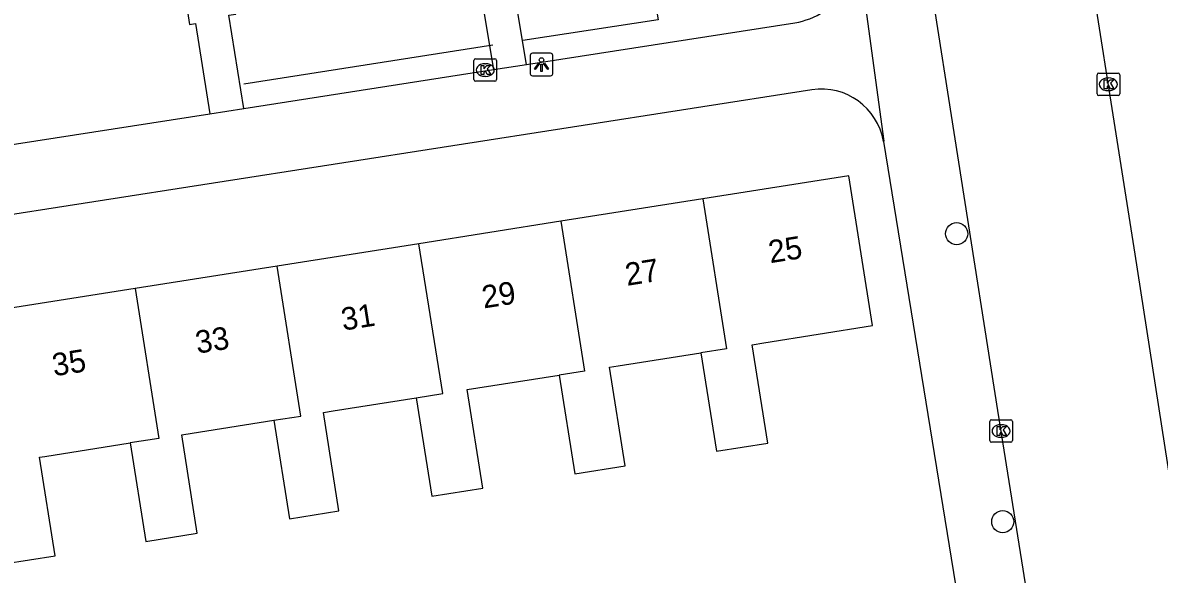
# Model space of a CAD drawing. Extents: x 160077 to 160945, y 386481 to 387498.
# Drawn here: x 160396 to 160446.3, y 387355.2 to 387379.6 of the extents above; entities that cross this region are included whole.
import ezdxf

# ---------------------------------------------------------------- set-up
doc = ezdxf.new("R2010")
doc.units = 0
for name, color, linetype in [('IMGEO_Boom', 7, 'Continuous'), ('IMGEO_Hek', 7, 'Continuous'), ('IMGEO_Kolk', 7, 'Continuous'), ('IMGEO_Lichtpunt', 7, 'Continuous'), ('IMGEO_Pand', 7, 'Continuous'), ('IMGEO_Pand_nummerreeks', 7, 'Continuous'), ('IMGEO_Rijbaan_lokaal_open', 7, 'Continuous'), ('IMGEO_Voetpad_open', 7, 'Continuous')]:
    doc.layers.add(name, color=color, linetype=linetype)

msp = doc.modelspace()

# ---------------------------------------------------------------- linework, layer by layer
at = {"layer": 'IMGEO_Boom'}
for centre in [(160437.295, 387370.245), (160439.333, 387357.508)]:
    msp.add_circle(centre, 0.489, dxfattribs=at)
at = {"layer": 'IMGEO_Hek'}
for points in [[(160423.651, 387382.448), (160424.101, 387379.701), (160418.122, 387378.788)], [(160416.789, 387378.59), (160405.787, 387376.859)]]:
    msp.add_lwpolyline(points, dxfattribs=at)
at = {"layer": 'IMGEO_Kolk'}
for p, q in [((160415.958, 387377.059), (160415.958, 387377.911)), ((160416.033, 387377.985), (160416.885, 387377.985)), ((160416.446, 387377.765), (160416.471, 387377.765)), ((160416.959, 387377.911), (160416.959, 387377.059)), ((160416.469, 387377.205), (160416.444, 387377.205)), ((160443.501, 387376.426), (160443.501, 387377.278)), ((160443.576, 387377.352), (160444.428, 387377.352)), ((160443.989, 387377.132), (160444.014, 387377.132)), ((160444.502, 387377.278), (160444.502, 387376.426)), ((160416.885, 387376.985), (160416.033, 387376.985)), ((160444.012, 387376.572), (160443.987, 387376.572)), ((160444.428, 387376.352), (160443.576, 387376.352)), ((160438.759, 387361.091), (160438.759, 387361.943)), ((160438.834, 387362.017), (160439.686, 387362.017)), ((160439.76, 387361.943), (160439.76, 387361.091)), ((160439.247, 387361.797), (160439.272, 387361.797)), ((160439.686, 387361.017), (160438.834, 387361.017)), ((160439.27, 387361.237), (160439.245, 387361.237))]:
    msp.add_line(p, q, dxfattribs=at)
for points in [[(160415.958, 387377.059), (160415.958, 387377.911)], [(160416.033, 387377.985), (160416.885, 387377.985)], [(160416.279, 387377.685), (160416.402, 387377.685), (160416.402, 387377.534), (160416.532, 387377.685), (160416.696, 387377.685), (160416.55, 387377.534), (160416.703, 387377.285), (160416.551, 387377.285), (160416.466, 387377.449), (160416.402, 387377.382), (160416.402, 387377.285), (160416.279, 387377.285), (160416.279, 387377.685)], [(160416.959, 387377.911), (160416.959, 387377.059)], [(160443.501, 387376.426), (160443.501, 387377.278)], [(160443.576, 387377.352), (160444.428, 387377.352)], [(160443.822, 387377.052), (160443.945, 387377.052), (160443.945, 387376.901), (160444.075, 387377.052), (160444.239, 387377.052), (160444.093, 387376.901), (160444.246, 387376.652), (160444.094, 387376.652), (160444.009, 387376.816), (160443.945, 387376.749), (160443.945, 387376.652), (160443.822, 387376.652), (160443.822, 387377.052)], [(160444.502, 387377.278), (160444.502, 387376.426)], [(160416.885, 387376.985), (160416.033, 387376.985)], [(160444.428, 387376.352), (160443.576, 387376.352)], [(160438.759, 387361.091), (160438.759, 387361.943)], [(160438.834, 387362.017), (160439.686, 387362.017)], [(160439.76, 387361.943), (160439.76, 387361.091)], [(160439.08, 387361.717), (160439.203, 387361.717), (160439.203, 387361.566), (160439.333, 387361.717), (160439.497, 387361.717), (160439.351, 387361.566), (160439.504, 387361.317), (160439.352, 387361.317), (160439.267, 387361.481), (160439.203, 387361.414), (160439.203, 387361.317), (160439.08, 387361.317), (160439.08, 387361.717)], [(160439.686, 387361.017), (160438.834, 387361.017)]]:
    msp.add_lwpolyline(points, dxfattribs=at)
for centre, start, end in [((160416.035, 387377.909), 91.552, 178.448), ((160416.035, 387377.909), 91.552, 178.448), ((160416.883, 387377.909), 1.552, 88.448), ((160416.883, 387377.909), 1.552, 88.448), ((160416.035, 387377.061), 181.552, 268.448), ((160416.035, 387377.061), 181.552, 268.448), ((160416.883, 387377.061), 271.552, 358.448), ((160416.883, 387377.061), 271.552, 358.448), ((160443.578, 387377.276), 91.552, 178.448), ((160443.578, 387377.276), 91.552, 178.448), ((160444.426, 387377.276), 1.552, 88.448), ((160444.426, 387377.276), 1.552, 88.448), ((160443.578, 387376.428), 181.552, 268.448), ((160443.578, 387376.428), 181.552, 268.448), ((160444.426, 387376.428), 271.552, 358.448), ((160444.426, 387376.428), 271.552, 358.448), ((160438.836, 387361.941), 91.552, 178.448), ((160438.836, 387361.941), 91.552, 178.448), ((160439.684, 387361.941), 1.552, 88.448), ((160439.684, 387361.941), 1.552, 88.448), ((160438.836, 387361.093), 181.552, 268.448), ((160438.836, 387361.093), 181.552, 268.448), ((160439.684, 387361.093), 271.552, 358.448), ((160439.684, 387361.093), 271.552, 358.448)]:
    msp.add_arc(centre, 0.0765, start, end, dxfattribs=at)
for centre, major_axis, ratio, start_param, end_param in [((160416.445, 387377.485), (-0.387, 0.002), 0.722429, 4.712389, 7.853982), ((160416.47, 387377.485), (-0.39, 0.002), 0.717154, 1.570796, 4.712389), ((160443.988, 387376.852), (-0.387, 0.002), 0.722429, 4.712389, 7.853982), ((160444.013, 387376.852), (-0.39, 0.002), 0.717154, 1.570796, 4.712389), ((160439.246, 387361.517), (-0.387, 0.002), 0.722429, 4.712389, 7.853982), ((160439.271, 387361.517), (-0.39, 0.002), 0.717154, 1.570796, 4.712389)]:
    msp.add_ellipse(centre, major_axis=major_axis, ratio=ratio, start_param=start_param, end_param=end_param, dxfattribs=at)
at = {"layer": 'IMGEO_Lichtpunt'}
for p, q in [((160418.447, 387378.13), (160418.447, 387377.323)), ((160418.447, 387378.13), (160418.447, 387377.323)), ((160419.349, 387378.225), (160418.541, 387378.225)), ((160419.349, 387378.225), (160418.541, 387378.225)), ((160419.443, 387377.323), (160419.443, 387378.13)), ((160419.443, 387377.323), (160419.443, 387378.13)), ((160418.541, 387377.229), (160419.349, 387377.229)), ((160418.541, 387377.229), (160419.349, 387377.229))]:
    msp.add_line(p, q, dxfattribs=at)
for points in [[(160418.821, 387377.794), (160418.86, 387377.766), (160418.672, 387377.504), (160418.634, 387377.531), (160418.821, 387377.794)], [(160418.923, 387377.746), (160418.97, 387377.746), (160418.97, 387377.424), (160418.923, 387377.424), (160418.923, 387377.746)], [(160419.033, 387377.766), (160419.071, 387377.793), (160419.258, 387377.531), (160419.219, 387377.503), (160419.033, 387377.766)]]:
    msp.add_lwpolyline(points, dxfattribs=at)
msp.add_circle((160418.946, 387377.928), 0.0994, dxfattribs=at)
for centre, start, end in [((160418.541, 387378.13), 90, 180), ((160418.541, 387378.13), 90, 180), ((160419.349, 387378.13), 0, 90), ((160419.349, 387378.13), 0, 90), ((160418.541, 387377.323), 180, 270), ((160418.541, 387377.323), 180, 270), ((160419.349, 387377.323), 270, 0), ((160419.349, 387377.323), 270, 360)]:
    msp.add_arc(centre, 0.0946, start, end, dxfattribs=at)
at = {"layer": 'IMGEO_Pand'}
for points in [[(160425.988, 387364.978), (160426.677, 387360.618), (160428.944, 387360.977), (160428.255, 387365.336), (160428.772, 387365.418), (160433.574, 387366.177), (160432.526, 387372.806), (160426.08, 387371.787)], [(160426.08, 387371.787), (160419.805, 387370.795)], [(160426.08, 387371.787), (160427.128, 387365.155), (160425.988, 387364.978)], [(160419.805, 387370.795), (160413.53, 387369.803)], [(160419.805, 387370.795), (160420.853, 387364.165), (160419.732, 387363.989)], [(160413.53, 387369.803), (160407.254, 387368.811)], [(160413.405, 387362.989), (160414.578, 387363.176), (160413.53, 387369.803)], [(160407.254, 387368.811), (160400.979, 387367.819)], [(160407.111, 387361.994), (160408.302, 387362.179), (160407.254, 387368.811)], [(160400.979, 387367.819), (160394.537, 387366.801), (160395.587, 387360.161), (160394.789, 387360.035), (160394.496, 387359.989), (160395.183, 387355.641), (160397.445, 387355.998), (160396.756, 387360.358), (160396.986, 387360.394), (160400.769, 387360.991)], [(160400.979, 387367.819), (160402.026, 387361.192), (160400.769, 387360.991)], [(160419.732, 387363.989), (160420.421, 387359.63), (160422.645, 387359.981), (160421.956, 387364.34), (160422.333, 387364.4), (160425.988, 387364.978)], [(160413.405, 387362.989), (160414.094, 387358.63), (160416.35, 387358.986), (160415.661, 387363.346), (160416.13, 387363.42), (160419.732, 387363.989)], [(160407.111, 387361.994), (160407.8, 387357.635), (160409.994, 387357.982), (160409.305, 387362.341), (160409.73, 387362.408), (160413.405, 387362.989)], [(160400.769, 387360.991), (160401.458, 387356.632), (160403.731, 387356.992), (160403.042, 387361.351), (160403.498, 387361.423), (160407.111, 387361.994)]]:
    msp.add_lwpolyline(points, dxfattribs=at)
at = {"layer": 'IMGEO_Rijbaan_lokaal_open'}
for points in [[(160450.725, 387333.607), (160445.185, 387369.339), (160439.731, 387403.919), (160433.965, 387439.947)], [(160449.285, 387297.666), (160448.468, 387302.807), (160443.348, 387335.908), (160439.116, 387362.429), (160435.904, 387382.909), (160432.676, 387403.453)]]:
    msp.add_lwpolyline(points, dxfattribs=at)
at = {"layer": 'IMGEO_Voetpad_open'}
for points in [[(160432.797, 387383.226), (160432.875, 387383.209), (160434.076, 387374.342), (160434.062, 387374.328)], [(160418.286, 387377.731), (160417.609, 387381.798), (160417.964, 387381.857), (160417.79, 387382.904), (160415.97, 387382.625), (160416.822, 387377.502)], [(160405.786, 387375.784), (160405.129, 387379.913), (160405.437, 387379.957), (160405.291, 387380.97), (160403.206, 387380.669), (160403.385, 387379.5), (160403.658, 387379.543), (160404.282, 387375.55)], [(160418.286, 387377.731), (160430.145, 387379.577)], [(160416.822, 387377.502), (160418.286, 387377.731)], [(160405.786, 387375.784), (160416.822, 387377.502)], [(160430.901, 387376.611), (160393.851, 387370.828)], [(160393.162, 387373.819), (160404.282, 387375.55)], [(160404.282, 387375.55), (160405.786, 387375.784)], [(160434.062, 387374.328), (160437.249, 387354.718)]]:
    msp.add_lwpolyline(points, dxfattribs=at)
for centre, radius, start, end in [((160429.66, 387382.724), 3.184, 278.7549, 328.3276), ((160431.319, 387373.86), 2.782, 9.6805, 98.6429)]:
    msp.add_arc(centre, radius, start, end, dxfattribs=at)

# ---------------------------------------------------------------- texts
at = {"layer": 'IMGEO_Pand_nummerreeks'}
for s, p in [('25', (160429.056, 387368.937)), ('27', (160422.725, 387367.936)), ('29', (160416.393, 387366.935)), ('31', (160410.173, 387365.952)), ('33', (160403.73, 387364.934)), ('35', (160397.399, 387363.933))]:
    msp.add_text(s, height=1, rotation=8.984, dxfattribs=at).set_placement(p)

doc.saveas('drawing.dxf')
